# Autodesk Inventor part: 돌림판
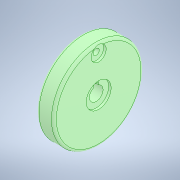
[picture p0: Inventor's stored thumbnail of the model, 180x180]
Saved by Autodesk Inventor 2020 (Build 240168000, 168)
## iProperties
Created: 2024-04
Part Number: 돌림판
Material: 일반
Document SubType Name: Modeling
Designer: oem
Density: 1 g/cm^3
Appearance: 기본값
Author: jhkim
Sending System: Autodesk Inventor 2025
Preprocessor: ST-DEVELOPER v20
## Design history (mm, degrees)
feature "솔리드1"
node "솔리드2"
